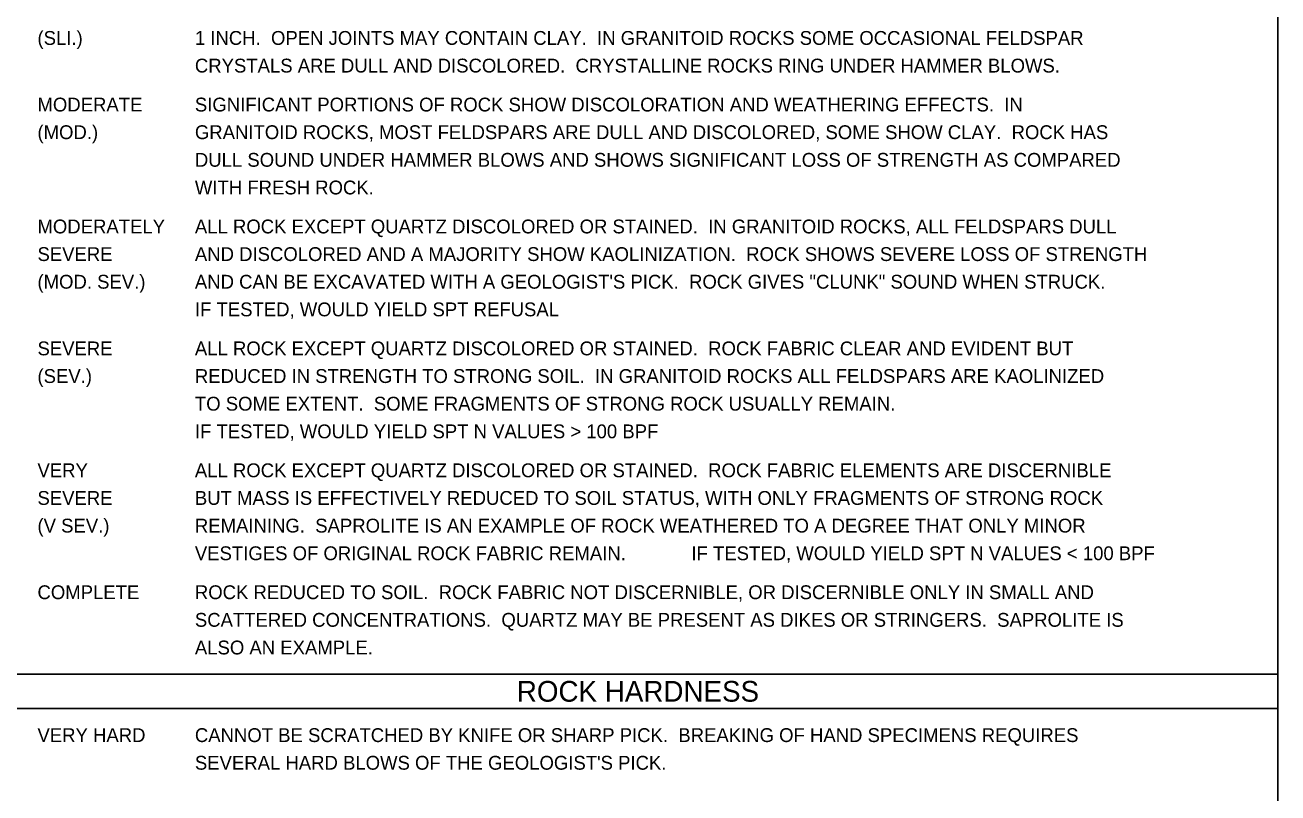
# Model space of a CAD drawing. Extents: x 278618 to 280654, y 171155 to 171855.
# Drawn here: x 280549.54 to 280588.8, y 171574.37 to 171598.45 of the extents above; entities that cross this region are included whole.
import ezdxf

# ---------------------------------------------------------------- set-up
doc = ezdxf.new("R2010")
doc.units = 0
doc.layers.add('Geotech Sheets and Borders Cell', color=7, linetype='Continuous')

msp = doc.modelspace()

# ---------------------------------------------------------------- linework, layer by layer
at = {"layer": 'Geotech Sheets and Borders Cell'}
for p, q in [((280588.802, 171621.702), (280588.802, 171541.488)), ((280549.148, 171578.101), (280588.802, 171578.101)), ((280549.148, 171577.016), (280588.802, 171577.016))]:
    msp.add_line(p, q, dxfattribs=at)

# ---------------------------------------------------------------- texts
for s, height, p in [('(SLI.)', 0.4338, (280549.929, 171597.827)), ('1 INCH.  OPEN JOINTS MAY CONTAIN CLAY.  IN GRANITOID ROCKS SOME OCCASIONAL FELDSPAR ', 0.43381, (280554.862, 171597.827)), ('CRYSTALS ARE DULL AND DISCOLORED.  CRYSTALLINE ROCKS RING UNDER HAMMER BLOWS.', 0.43381, (280554.862, 171596.96)), ('MODERATE', 0.4338, (280549.929, 171595.738)), ('SIGNIFICANT PORTIONS OF ROCK SHOW DISCOLORATION AND WEATHERING EFFECTS.  IN ', 0.43381, (280554.862, 171595.738)), ('(MOD.)', 0.4338, (280549.929, 171594.872)), ('GRANITOID ROCKS, MOST FELDSPARS ARE DULL AND DISCOLORED, SOME SHOW CLAY.  ROCK HAS ', 0.43381, (280554.862, 171594.872)), ('DULL SOUND UNDER HAMMER BLOWS AND SHOWS SIGNIFICANT LOSS OF STRENGTH AS COMPARED ', 0.43381, (280554.862, 171594.005)), ('WITH FRESH ROCK.', 0.43381, (280554.862, 171593.138)), ('MODERATELY', 0.4338, (280549.929, 171591.916)), ('ALL ROCK EXCEPT QUARTZ DISCOLORED OR STAINED.  IN GRANITOID ROCKS, ALL FELDSPARS DULL ', 0.43381, (280554.862, 171591.916)), ('SEVERE', 0.4338, (280549.929, 171591.05)), ('AND DISCOLORED AND A MAJORITY SHOW KAOLINIZATION.  ROCK SHOWS SEVERE LOSS OF STRENGTH', 0.43381, (280554.862, 171591.05)), ('(MOD. SEV.)', 0.43381, (280549.929, 171590.183)), ('AND CAN BE EXCAVATED WITH A GEOLOGIST\'S PICK.  ROCK GIVES "CLUNK" SOUND WHEN STRUCK.', 0.43381, (280554.862, 171590.183)), ('IF TESTED, WOULD YIELD SPT REFUSAL', 0.43381, (280554.862, 171589.316)), ('SEVERE', 0.4338, (280549.929, 171588.093)), ('ALL ROCK EXCEPT QUARTZ DISCOLORED OR STAINED.  ROCK FABRIC CLEAR AND EVIDENT BUT ', 0.43381, (280554.862, 171588.093)), ('(SEV.)', 0.4338, (280549.929, 171587.226)), ('REDUCED IN STRENGTH TO STRONG SOIL.  IN GRANITOID ROCKS ALL FELDSPARS ARE KAOLINIZED', 0.43381, (280554.862, 171587.226)), ('TO SOME EXTENT.  SOME FRAGMENTS OF STRONG ROCK USUALLY REMAIN.', 0.43381, (280554.862, 171586.359)), ('IF TESTED, WOULD YIELD SPT N VALUES > 100 BPF', 0.43381, (280554.862, 171585.492)), ('VERY', 0.4338, (280549.929, 171584.271)), ('ALL ROCK EXCEPT QUARTZ DISCOLORED OR STAINED.  ROCK FABRIC ELEMENTS ARE DISCERNIBLE ', 0.43381, (280554.862, 171584.271)), ('SEVERE', 0.4338, (280549.929, 171583.404)), ('BUT MASS IS EFFECTIVELY REDUCED TO SOIL STATUS, WITH ONLY FRAGMENTS OF STRONG ROCK ', 0.43381, (280554.862, 171583.404)), ('(V SEV.)', 0.4338, (280549.929, 171582.537)), ('REMAINING.  SAPROLITE IS AN EXAMPLE OF ROCK WEATHERED TO A DEGREE THAT ONLY MINOR ', 0.43381, (280554.862, 171582.537)), ('VESTIGES OF ORIGINAL ROCK FABRIC REMAIN.   ', 0.43381, (280554.862, 171581.67)), ('IF TESTED, WOULD YIELD SPT N VALUES < 100 BPF', 0.43381, (280570.422, 171581.67)), ('COMPLETE', 0.4338, (280549.929, 171580.448)), ('ROCK REDUCED TO SOIL.  ROCK FABRIC NOT DISCERNIBLE, OR DISCERNIBLE ONLY IN SMALL AND ', 0.43381, (280554.862, 171580.448)), ('SCATTERED CONCENTRATIONS.  QUARTZ MAY BE PRESENT AS DIKES OR STRINGERS.  SAPROLITE IS ', 0.43381, (280554.862, 171579.582)), ('ALSO AN EXAMPLE.', 0.43381, (280554.862, 171578.715)), ('ROCK HARDNESS', 0.6507, (280564.951, 171577.233)), ('VERY HARD', 0.4338, (280549.929, 171575.968)), ('CANNOT BE SCRATCHED BY KNIFE OR SHARP PICK.  BREAKING OF HAND SPECIMENS REQUIRES ', 0.43381, (280554.862, 171575.968)), ("SEVERAL HARD BLOWS OF THE GEOLOGIST'S PICK.", 0.43381, (280554.862, 171575.101))]:
    msp.add_text(s, height=height, dxfattribs=at).set_placement(p)

doc.saveas('drawing.dxf')
